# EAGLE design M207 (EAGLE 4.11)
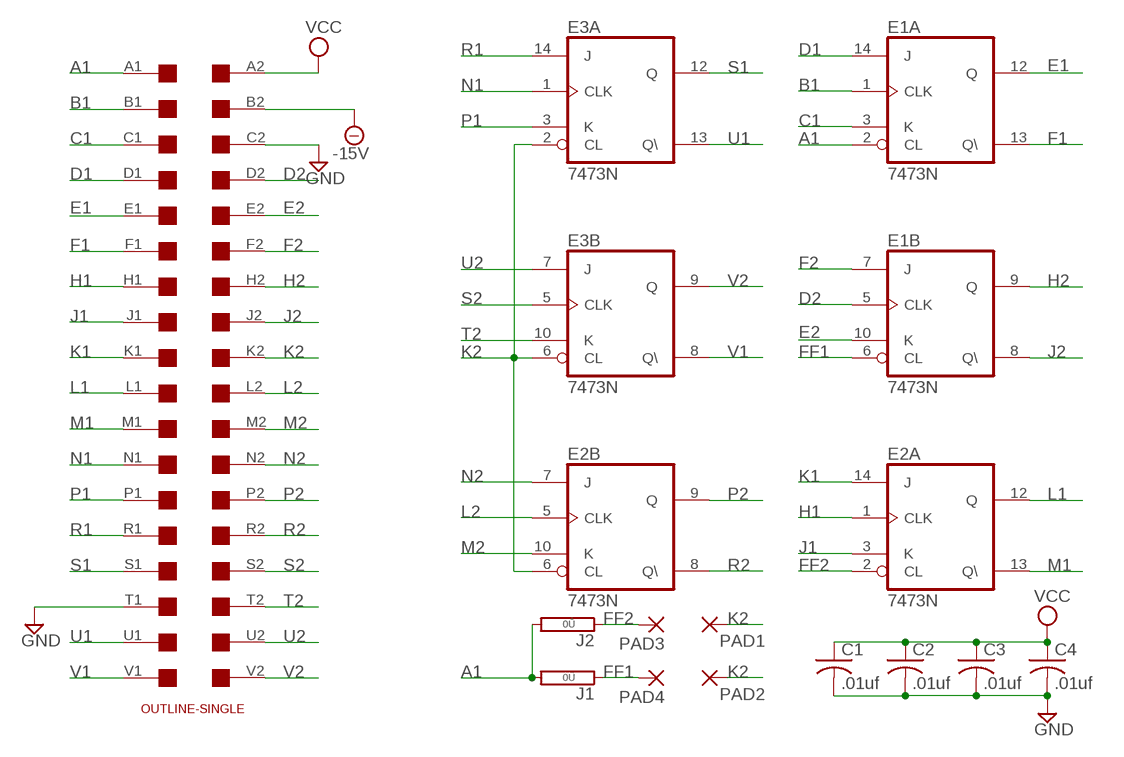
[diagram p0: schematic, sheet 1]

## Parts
C1  .01uf  C-US050-025X075  [C050-025X075]
C2  .01uf  C-US050-025X075  [C050-025X075]
C3  .01uf  C-US050-025X075  [C050-025X075]
C4  .01uf  C-US050-025X075  [C050-025X075]
E1  7473N  74LS73N  [DIL14]
E2  7473N  74LS73N  [DIL14]
E3  7473N  74LS73N  [DIL14]
J1  0R  [0R/10]
J2  0R  [0R/10]
PAD1  1,6/0,8  [1,6/0,8]
PAD2  1,6/0,8  [1,6/0,8]
PAD3  1,6/0,8  [1,6/0,8]
PAD4  1,6/0,8  [1,6/0,8]
U$1  SINGLE  [EDGE-CON2]
U$4  OUTLINE-SINGLE  [SINGLE]

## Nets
-15V: U$1.B2
A1: E1.2(A:CL) J1.2 J2.2 U$1.A1
B1: E1.1(A:CLK) U$1.B1
C1: E1.3(A:K) U$1.C1
D1: E1.14(A:J) U$1.D1
D2: E1.5(B:CLK) U$1.D2
E1: E1.12(A:Q) U$1.E1
E2: E1.10(B:K) U$1.E2
F1: E1.13(A:Q\) U$1.F1
F2: E1.7(B:J) U$1.F2
FF1: E1.6(B:CL) J1.1 PAD4.1(P)
FF2: E2.2(A:CL) J2.1 PAD3.1(P)
GND: C1.2 C2.2 C3.2 C4.2 U$1.C2 U$1.T1
H1: E2.1(A:CLK) U$1.H1
H2: E1.9(B:Q) U$1.H2
J1: E2.3(A:K) U$1.J1
J2: E1.8(B:Q\) U$1.J2
K1: E2.14(A:J) U$1.K1
K2: E2.6(B:CL) E3.2(A:CL) E3.6(B:CL) PAD1.1(P) PAD2.1(P) U$1.K2
L1: E2.12(A:Q) U$1.L1
L2: E2.5(B:CLK) U$1.L2
M1: E2.13(A:Q\) U$1.M1
M2: E2.10(B:K) U$1.M2
N1: E3.1(A:CLK) U$1.N1
N2: E2.7(B:J) U$1.N2
P1: E3.3(A:K) U$1.P1
P2: E2.9(B:Q) U$1.P2
R1: E3.14(A:J) U$1.R1
R2: E2.8(B:Q\) U$1.R2
S1: E3.12(A:Q) U$1.S1
S2: E3.5(B:CLK) U$1.S2
T2: E3.10(B:K) U$1.T2
U1: E3.13(A:Q\) U$1.U1
U2: E3.7(B:J) U$1.U2
V1: E3.8(B:Q\) U$1.V1
V2: E3.9(B:Q) U$1.V2
VCC: C1.1 C2.1 C3.1 C4.1 U$1.A2

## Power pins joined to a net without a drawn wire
GND: E1.11(P:GND) E2.11(P:GND) E3.11(P:GND)
VCC: E1.4(P:VCC) E2.4(P:VCC) E3.4(P:VCC)

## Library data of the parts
C1-C4 = rcl:C-US: CAPACITOR, American symbol
E1-E3 = 74xx-us:74*73: Dual J-K FLIP FLOP, clear
J1 J2 = jumper:0R: Bridge 0R 10mm
PAD1-PAD4 = wirepad:1,6/0,8: THROUGH-HOLE PAD
U$1 = dec-con:SINGLE: Single-Height DEC board
U$4 = dec-con:OUTLINE-*: Board outlines for DEC boards.

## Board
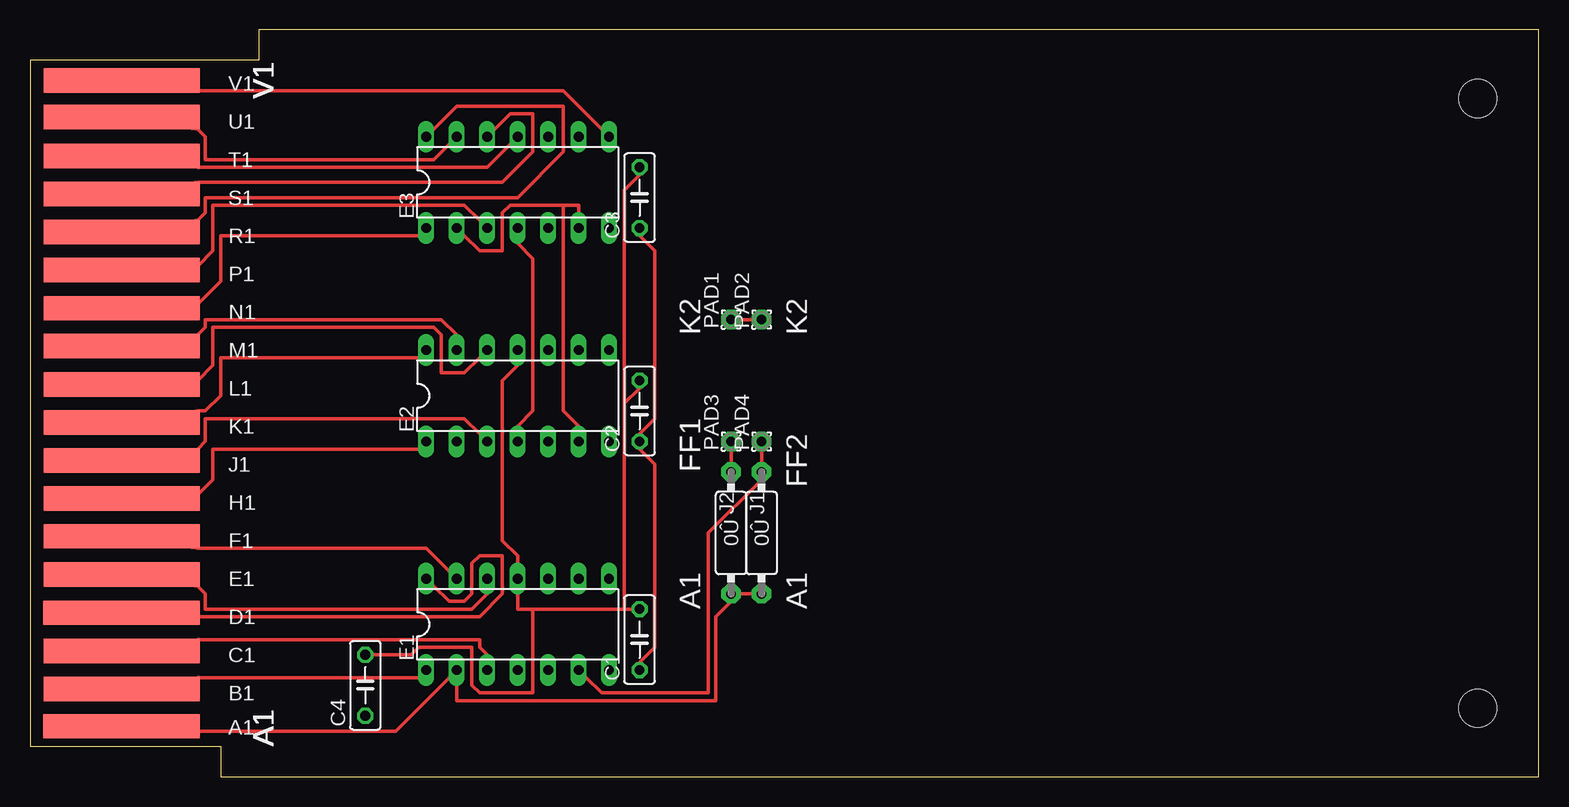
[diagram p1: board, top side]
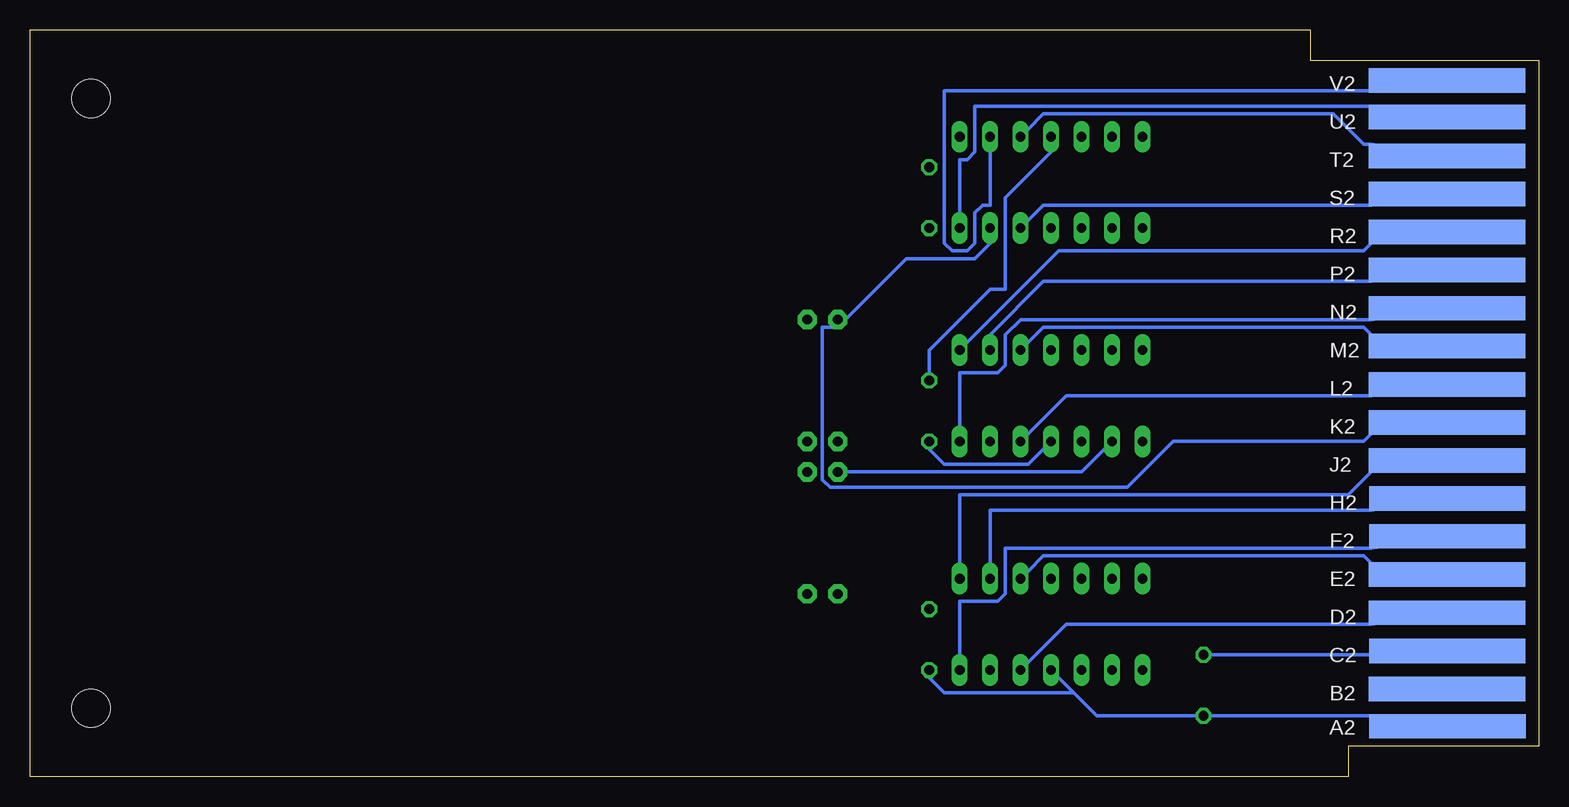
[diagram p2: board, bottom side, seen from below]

Size 125.73 x 62.23 mm. Coordinates in mm from the lower left corner, seen from the top.
Copper layers (1*16): Top 0.035mm / dielectric 1.5mm / Bottom 0.035mm
Design rules "10mils": minimum track width 12mil, minimum drill 28mil, track to track 10mil, track to pad 10mil, pad to pad 10mil, via to via 10mil, smd to smd 10mil, copper to edge 25mil, drill to drill 10mil, minimum pad ring 10mil, minimum via ring 8mil, stop-mask expansion 0mil, vias tented up to drill 0mil, thermal gap 10mil

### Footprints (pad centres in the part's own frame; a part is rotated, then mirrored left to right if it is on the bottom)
C050-025X075 = drill 0.813 octagon: 1 -2.54,0; 2 2.54,0
DIL14 = drill 0.813 long: 1 -7.62,-3.81; 2 -5.08,-3.81; 3 -2.54,-3.81; 4 0,-3.81; 5 2.54,-3.81; 6 5.08,-3.81; 7 7.62,-3.81; 8 7.62,3.81; 9 5.08,3.81; 10 2.54,3.81; 11 0,3.81; 12 -2.54,3.81; 13 -5.08,3.81; 14 -7.62,3.81
0R/10 = drill 0.813 pad 1.6 octagon: 1 -5.08,0; 2 5.08,0
1,6/0,8 = drill 0.813 pad 1.6 octagon: 1 0,0
EDGE-CON2 = smd 13.017 x 2.032: A1 7.633,4.207; B1 7.639,7.327; C1 7.636,10.489; D1 7.633,13.665; E1 7.642,16.84; F1 7.642,20.041; H1 7.642,23.19; J1 7.642,26.34; K1 7.642,29.515; L1 7.642,32.69; M1 7.642,35.89; N1 7.642,39.04; P1 7.642,42.24; R1 7.642,45.39; S1 7.642,48.565; T1 7.642,51.74; U1 7.642,54.966; V1 7.642,58.026 | smd 13.017 x 2.032 bottom: A2 7.614,4.207; B2 7.642,7.328; C2 7.617,10.49; D2 7.642,13.665; E2 7.642,16.84; F2 7.617,20.041; H2 7.617,23.19; J2 7.642,26.34; K2 7.642,29.515; L2 7.642,32.69; M2 7.642,35.89; N2 7.642,39.04; P2 7.642,42.24; R2 7.642,45.39; S2 7.642,48.565; T2 7.642,51.74; U2 7.642,54.966; V2 7.642,58.026
SINGLE = hole 3.175: 120.65,56.515; 120.65,5.715

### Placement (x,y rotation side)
C1  50.8,11.43 90 top
C2  50.8,30.48 90 top
C3  50.8,48.26 90 top
C4  27.94,7.62 90 top
E1  40.64,12.7 0 top
E2  40.64,31.75 0 top
E3  40.64,49.53 0 top
J1  60.96,20.32 270 top
J2  58.42,20.32 270 top
PAD1  58.42,38.1 90 top
PAD2  60.96,38.1 90 top
PAD3  58.42,27.94 90 top
PAD4  60.96,27.94 90 top
U$1  0,0 0 top
U$4  0,0 0 top

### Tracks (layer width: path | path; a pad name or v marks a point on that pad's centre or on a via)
A1
  Top 0.305: J1.2 60.33,15.24 59.06,15.24 J2.2 58.42,14.61 57.15,13.34 57.15,6.35 35.56,6.35 35.56,7.62 E1.2 34.93,8.26 30.48,3.81 13.97,3.81 U$1.A1
B1
  Top 0.305: E1.1 32.39,8.26 13.97,8.26 U$1.B1
C1
  Top 0.305: E1.3 38.1,10.16 37.47,10.79 37.47,11.43 13.97,11.43 U$1.C1
D1
  Top 0.305: E1.14 33.66,15.88 34.93,14.61 36.2,14.61 36.83,15.24 36.83,17.78 37.47,18.41 39.37,18.41 39.37,15.24 37.47,13.34 13.97,13.34 U$1.D1
D2
  Bottom 0.305: E1.5 42.55,9.53 39.37,12.7 13.97,12.7 U$1.D2
E1
  Top 0.305: E1.12 38.1,15.24 36.83,13.97 14.61,13.97 14.61,15.24 13.97,15.88 U$1.E1
E2
  Bottom 0.305: E1.10 42.55,17.14 41.28,18.41 14.61,18.41 13.97,17.78 U$1.E2
F1
  Top 0.305: E1.13 34.93,17.14 33.02,19.05 13.97,19.05 U$1.F1
F2
  Bottom 0.305: E1.7 48.26,10.16 48.26,14.61 45.09,14.61 44.45,15.24 44.45,19.05 13.97,19.05 U$1.F2
FF1
  Top 0.305: E1.6 46.36,8.26 47.63,6.99 56.52,6.99 56.52,20.32 60.96,24.77 J1.1 60.96,26.04 60.96,27.3 PAD4.1
FF2
  Top 0.305: PAD3.1 58.42,27.3 58.42,26.04 J2.1
  Bottom 0.305: E2.2 36.2,27.3 38.1,25.4 57.79,25.4 J2.1
GND
  Top 0.305: E3.11 40.01,52.7 38.1,50.8 13.97,50.8 U$1.T1 | 41.91,13.97 40.64,13.97 40.64,15.24 E1.11 40.64,17.78 40.64,18.41 39.37,19.68 39.37,33.02 40.64,34.29 E2.11 | 41.91,13.97 49.53,13.97 | 49.53,13.97 50.17,13.97 C1.2 | 49.53,31.11 50.8,32.38 C2.2 | 49.53,13.97 49.53,31.11 | 49.53,31.11 49.53,48.9 50.8,50.16 C3.2 | 41.91,13.97 41.91,6.99 37.47,6.99 36.83,7.62 36.83,10.79 32.39,10.79 31.75,10.16 28.58,10.16 C4.2
  Bottom 0.305: C4.2 27.31,10.16 13.97,10.16 U$1.C2 | E3.11 40.64,52.07 44.45,48.26 44.45,40.64 45.72,40.64 50.8,35.56 50.8,33.66 C2.2
H1
  Top 0.305: E2.1 32.39,27.3 15.24,27.3 15.24,24.77 13.97,23.5 U$1.H1
H2
  Bottom 0.305: E1.9 45.72,17.78 45.72,22.23 13.97,22.23 U$1.H2
J1
  Top 0.305: E2.3 37.47,28.57 36.2,29.84 14.61,29.84 14.61,27.94 13.97,27.3 U$1.J1
J2
  Bottom 0.305: E1.8 48.26,17.78 48.26,23.5 15.88,23.5 13.97,25.4 U$1.J2
K1
  Top 0.305: E2.14 32.39,34.92 15.88,34.92 15.88,31.75 14.61,30.48 13.97,30.48 U$1.K1
K2
  Top 0.305: PAD1.1 59.06,38.1 60.33,38.1 PAD2.1 | 44.45,47.62 45.72,47.62 45.72,46.99 E3.6 | 44.45,47.62 40.01,47.62 39.37,46.99 39.37,43.81 37.47,43.81 36.2,45.09 E3.2 | 44.45,47.62 44.45,30.48 45.72,29.21 E2.6
  Bottom 0.305: E3.6 45.72,44.45 46.99,43.18 52.71,43.18 57.79,38.1 PAD1.1 58.42,37.47 59.69,37.47 59.69,24.77 59.06,24.13 34.29,24.13 30.48,27.94 14.61,27.94 13.97,28.57 U$1.K2
L1
  Top 0.305: E2.12 37.47,34.92 36.2,33.66 34.29,33.66 34.29,36.83 33.66,37.47 15.24,37.47 15.24,34.29 13.97,33.02 U$1.L1
L2
  Bottom 0.305: E2.5 42.55,28.57 39.37,31.75 13.97,31.75 U$1.L2
M1
  Top 0.305: E2.13 35.56,36.83 34.29,38.1 14.61,38.1 14.61,37.47 13.97,36.83 U$1.M1
M2
  Bottom 0.305: E2.10 42.55,36.2 41.28,37.47 14.61,37.47 13.97,36.83 U$1.M2
N1
  Top 0.305: E3.1 32.39,45.09 15.88,45.09 15.88,41.27 13.97,39.37 U$1.N1
N2
  Bottom 0.305: E2.7 48.26,29.21 48.26,33.66 45.09,33.66 44.45,34.29 44.45,36.83 43.18,38.1 13.97,38.1 U$1.N2
P1
  Top 0.305: E3.3 37.47,46.35 36.2,47.62 15.24,47.62 15.24,43.81 13.97,42.55 U$1.P1
P2
  Bottom 0.305: E2.9 45.72,36.83 41.28,41.27 13.97,41.27 U$1.P2
R1
  Top 0.305: E3.14 33.66,53.98 35.56,55.88 44.45,55.88 44.45,52.07 40.64,48.26 14.61,48.26 14.61,46.99 13.97,46.35 U$1.R1
R2
  Bottom 0.305: E2.8 47.63,36.2 40.01,43.81 14.61,43.81 13.97,44.45 U$1.R2
S1
  Top 0.305: E3.12 38.74,53.98 40.01,55.24 41.91,55.24 41.91,52.07 39.37,49.53 13.97,49.53 U$1.S1
S2
  Bottom 0.305: E3.5 42.55,46.35 41.28,47.62 13.97,47.62 U$1.S2
T2
  Bottom 0.305: E3.10 42.55,53.98 41.28,55.24 17.15,55.24 14.61,52.7 13.97,52.7 U$1.T2
U1
  Top 0.305: E3.13 34.93,52.7 33.66,51.44 14.61,51.44 14.61,53.34 13.97,53.98 U$1.U1
U2
  Bottom 0.305: E3.7 48.26,46.99 48.26,51.44 47.63,51.44 46.99,52.07 46.99,55.88 13.97,55.88 U$1.U2
V1
  Top 0.305: E3.8 47.63,53.98 44.45,57.15 13.97,57.15 U$1.V1
V2
  Bottom 0.305: E3.9 45.72,52.07 45.72,47.62 46.36,47.62 46.99,46.99 46.99,44.45 47.63,43.81 48.9,43.81 49.53,44.45 49.53,57.15 13.97,57.15 U$1.V2
VCC
  Top 0.305: E3.4 40.64,44.45 41.91,43.18 41.91,30.48 40.64,29.21 E2.4 | C3.1 50.8,45.09 52.07,43.81 52.07,29.84 50.8,28.57 C2.1 50.8,27.3 52.07,26.04 52.07,10.79 50.8,9.53 C1.1
  Bottom 0.305: E2.4 41.28,27.3 42.55,26.04 49.53,26.04 50.8,27.3 C2.1 | U$1.A2 13.97,5.08 27.31,5.08 C4.1 28.58,5.08 36.83,5.08 38.74,6.99 | 38.74,6.99 40.01,8.26 E1.4 | 38.74,6.99 49.53,6.99 50.8,8.26 C1.1

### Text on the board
tPlace: K2 | K2 | FF1 | FF2 | A1 | A1
tNames: V1 | V1 | V1 | V1 | V1 | V1 | V1 | V1 | V1 | V1 | V1 | V1 | V1 | V1 | V1 | V1 | V1 | V1 | V1 | V1 | V1 | V1 | V1 | V1 | V1 | V1 | V1 | V1 | V1 | V1 | V1 | V1 | A1 | A1 | A1 | A1 | A1 | A1 | A1 | A1 | A1 | A1 | A1 | A1 | A1 | A1 | A1 | A1 | A1 | A1 | A1 | A1 | A1 | A1 | A1 | A1 | A1 | A1 | A1 | A1 | A1 | A1 | A1 | A1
